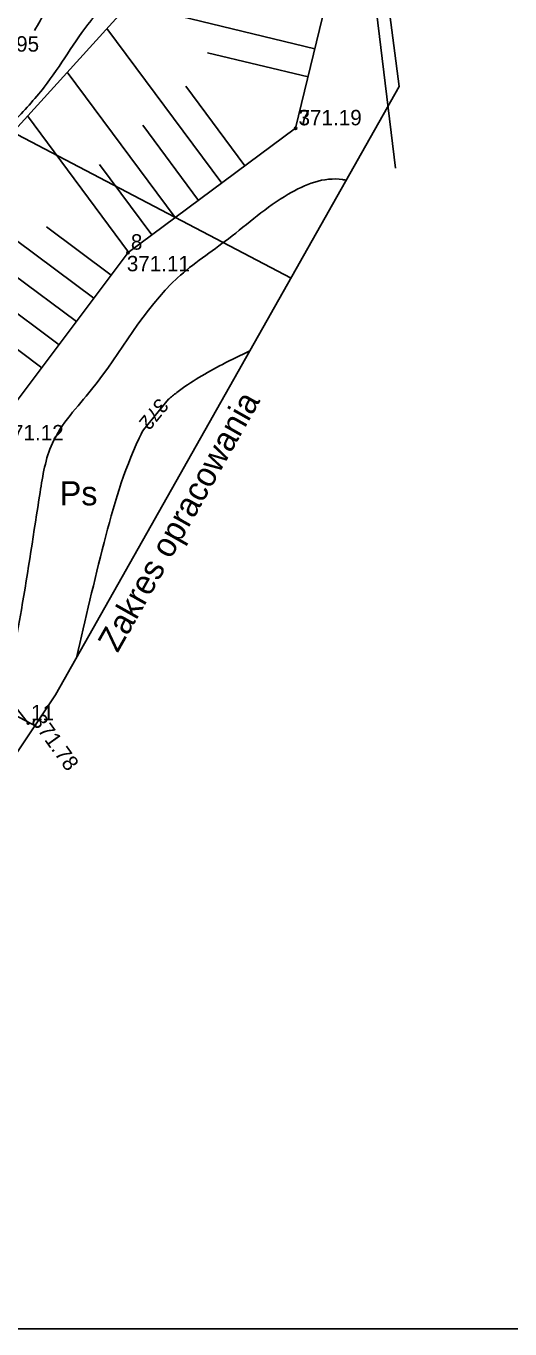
# Model space of a CAD drawing. Extents: x 4635329 to 4651863, y 5356628 to 5367582.
# Drawn here: x 4651767.8 to 4651792.8, y 5357005.8 to 5357073.3 of the extents above; entities that cross this region are included whole.
import ezdxf

# ---------------------------------------------------------------- set-up
doc = ezdxf.new("R2010")
doc.units = 0
for name, color, linetype in [('Level 1', 7, 'Continuous'), ('Level 12', 7, 'Continuous'), ('Level 13', 7, 'Continuous'), ('Level 39', 7, 'Continuous'), ('Level 4', 7, 'Continuous'), ('Level 44', 7, 'Continuous'), ('Level 45', 7, 'Continuous'), ('Level 46', 7, 'Continuous'), ('Level 47', 7, 'Continuous'), ('Level 48', 7, 'Continuous'), ('Level 6', 7, 'Continuous'), ('Level 63', 7, 'Continuous')]:
    doc.layers.add(name, color=color, linetype=linetype)

msp = doc.modelspace()

# ---------------------------------------------------------------- linework, layer by layer
at = {"layer": 'Level 1'}
for p, q in [((4651787.096, 5357070.175), (4651782.36, 5357106.665)), ((4651769.297, 5357038.67), (4651787.096, 5357070.175)), ((4651748.924, 5357008.222), (4651769.297, 5357038.67))]:
    msp.add_line(p, q, dxfattribs=at)
at = {"layer": 'Level 13'}
msp.add_lwpolyline([(4651671.382, 5357244.835), (4651857.008, 5357244.835), (4651857.008, 5357005.82), (4651671.382, 5357005.82)], close=True, dxfattribs=at)
at = {"layer": 'Level 39'}
msp.add_lwpolyline([(4651784.03, 5357086.98), (4651785.16, 5357080.31), (4651786.899, 5357065.954)], dxfattribs=at)
at = {"layer": 'Level 4'}
for p, q in [((4651760.729, 5357071.135), (4651781.491, 5357060.254)), ((4651755.332, 5357043.962), (4651768.308, 5357037.023))]:
    msp.add_line(p, q, dxfattribs=at)
at = {"layer": 'Level 44'}
for centre in [(4651781.73, 5357068.02), (4651773.05, 5357061.58), (4651767.88, 5357037.2)]:
    msp.add_circle(centre, 0.04, dxfattribs=at)
at = {"layer": 'Level 46'}
msp.add_line((4651773.846, 5357052.396), (4651775.139, 5357053.982), dxfattribs=at)
for points in [[(4651759.64, 5357069.854), (4651761.095, 5357072.307), (4651763.521, 5357076.401), (4651765.794, 5357079.585), (4651768.674, 5357082.223), (4651772.525, 5357084.498), (4651783.153, 5357090.274), (4651784.378, 5357091.117)], [(4651757.599, 5357060.829), (4651759.467, 5357062.262), (4651762.013, 5357069.388), (4651763.863, 5357071.997), (4651765.651, 5357073.573), (4651768.501, 5357077.425), (4651770.563, 5357079.778)], [(4651768.207, 5357073.084), (4651769.459, 5357075.043), (4651774.745, 5357079.435)], [(4651767.105, 5357068.328), (4651768.709, 5357070.15), (4651771.135, 5357073.607), (4651771.248, 5357073.748)], [(4651766.724, 5357038.681), (4651767.527, 5357043.066), (4651768.496, 5357049.151), (4651769.132, 5357051.698), (4651771.164, 5357054.488), (4651775.611, 5357060.263), (4651778.248, 5357062.295), (4651781.341, 5357064.6), (4651784.16, 5357065.358), (4651784.354, 5357065.321)], [(4651775.139, 5357053.982), (4651775.574, 5357054.329), (4651777.941, 5357055.786), (4651779.366, 5357056.493)], [(4651770.381, 5357040.589), (4651771.812, 5357046.56), (4651773.632, 5357051.962), (4651773.846, 5357052.396)]]:
    msp.add_spline(points, degree=3, dxfattribs=at)
at = {"layer": 'Level 48'}
for p, q in [((4651782.724, 5357072.132), (4651773.101, 5357074.459)), ((4651777.9, 5357065.178), (4651771.954, 5357073.192)), ((4651782.372, 5357070.674), (4651777.164, 5357071.934)), ((4651775.49, 5357063.391), (4651769.901, 5357070.924)), ((4651779.104, 5357066.072), (4651776.043, 5357070.199)), ((4651773.081, 5357061.603), (4651767.848, 5357068.656)), ((4651776.695, 5357064.284), (4651773.811, 5357068.171)), ((4651774.286, 5357062.497), (4651771.58, 5357066.143)), ((4651771.276, 5357059.209), (4651764.638, 5357064.176)), ((4651772.175, 5357060.41), (4651768.823, 5357062.918)), ((4651769.479, 5357056.807), (4651762.97, 5357061.677)), ((4651770.377, 5357058.008), (4651767.091, 5357060.467)), ((4651768.58, 5357055.606), (4651765.358, 5357058.017))]:
    msp.add_line(p, q, dxfattribs=at)
for points in [[(4651757.66, 5357053.72), (4651767.01, 5357067.73), (4651777.8, 5357079.65), (4651784.84, 5357080.88)], [(4651784.84, 5357080.88), (4651781.73, 5357068.02), (4651773.05, 5357061.58), (4651766.54, 5357052.88), (4651762.19, 5357044.49)], [(4651762.19, 5357044.49), (4651767.88, 5357037.2)]]:
    msp.add_lwpolyline(points, dxfattribs=at)
at = {"layer": 'Level 63'}
for centre in [(4651781.73, 5357068.02), (4651773.05, 5357061.58), (4651767.88, 5357037.2)]:
    msp.add_circle(centre, 0.06, dxfattribs=at)

# ---------------------------------------------------------------- texts
at = {"layer": 'Level 12'}
msp.add_text('Ps', height=1.25, dxfattribs=at).set_placement((4651769.517, 5357048.484))
at = {"layer": 'Level 45'}
for s, p in [('366.95', (4651765.173, 5357071.988)), ('371.19', (4651781.88, 5357068.17)), ('371.11', (4651772.988, 5357060.609)), ('371.12', (4651766.448, 5357051.848))]:
    msp.add_text(s, height=0.8, dxfattribs=at).set_placement(p)
msp.add_text('371.78', height=0.8, rotation=305.65672, dxfattribs=at).set_placement((4651767.998, 5357037.312))
at = {"layer": 'Level 47'}
msp.add_text('372', height=0.75, rotation=230.68961, dxfattribs=at).set_placement((4651774.631, 5357054.093))
at = {"layer": 'Level 6'}
msp.add_text('Zakres opracowania', height=1.25, rotation=60.53538, dxfattribs=at).set_placement((4651772.514, 5357040.807))
at = {"layer": 'Level 63'}
for s, p in [('7', (4651781.88, 5357068.17)), ('8', (4651773.2, 5357061.73)), ('11', (4651768.03, 5357037.35))]:
    msp.add_text(s, height=0.8, dxfattribs=at).set_placement(p)

doc.saveas('drawing.dxf')
